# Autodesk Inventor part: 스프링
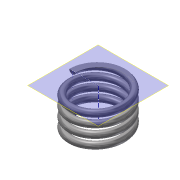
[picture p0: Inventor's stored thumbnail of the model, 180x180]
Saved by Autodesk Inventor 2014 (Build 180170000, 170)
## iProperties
Created: 2015-04
Part Number: 스프링
Material: 강철, 탄소
Document SubType Name: Modeling
Designer: Administrator
Density: 7.87 g/cm^3
Appearance: 반연마
Mass: 4.7875 g
Surface Area: 12.5242 cm^2
Volume: 0.608323 cm^3
Author: Administrator
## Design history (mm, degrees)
sketch "스케치1"
  geometry: L1 (0, 0)-(-8, 0); L2 (-8, 0)-(-8, 11.5); L3 (-8, 11.5)-(0, 11.5); L4 (0, 11.5)-(0, 0); C1 r 1 at (-8, 0)
  constraints: 8 end point, 2 parallel, 1 centre point, 1 coincident, 1 horizontal, 1 perpendicular
  dimensions: "d1" = 16 diameter of L2 L4; "d2" = 11.50049 distance between parallel lines of L3 L1 (derived); "d3" = 2 diameter of C1
feature "코일1" pitch "d4" = 10; turns "d6" = 4; dims "d5" = 11.50049 (= d2), "d7" = 0, angle "d8" = 90 deg, angle "d9" = 90 deg, "d10" = 0, "d11" = 0
sketch "스케치2"
  geometry: L1 (9, 0)-(7, 0) reference; 1 further point
  constraints: 1 horizontal alignment
extrude "돌출1" cut sketch "스케치2" stored distance "d12" = 10; taper "d13" = 0 deg
node "작업 평면1"
sketch "스케치4"
  geometry: L1 (-9, 0)-(-7, 0) reference; 1 further point
  constraints: 1 horizontal alignment
extrude "돌출2" cut sketch "스케치4" stored distance "d14" = 10; taper "d15" = 0 deg
node "솔리드1"
node "절단 모서리 투영1"
node "절단 모서리 투영2"
